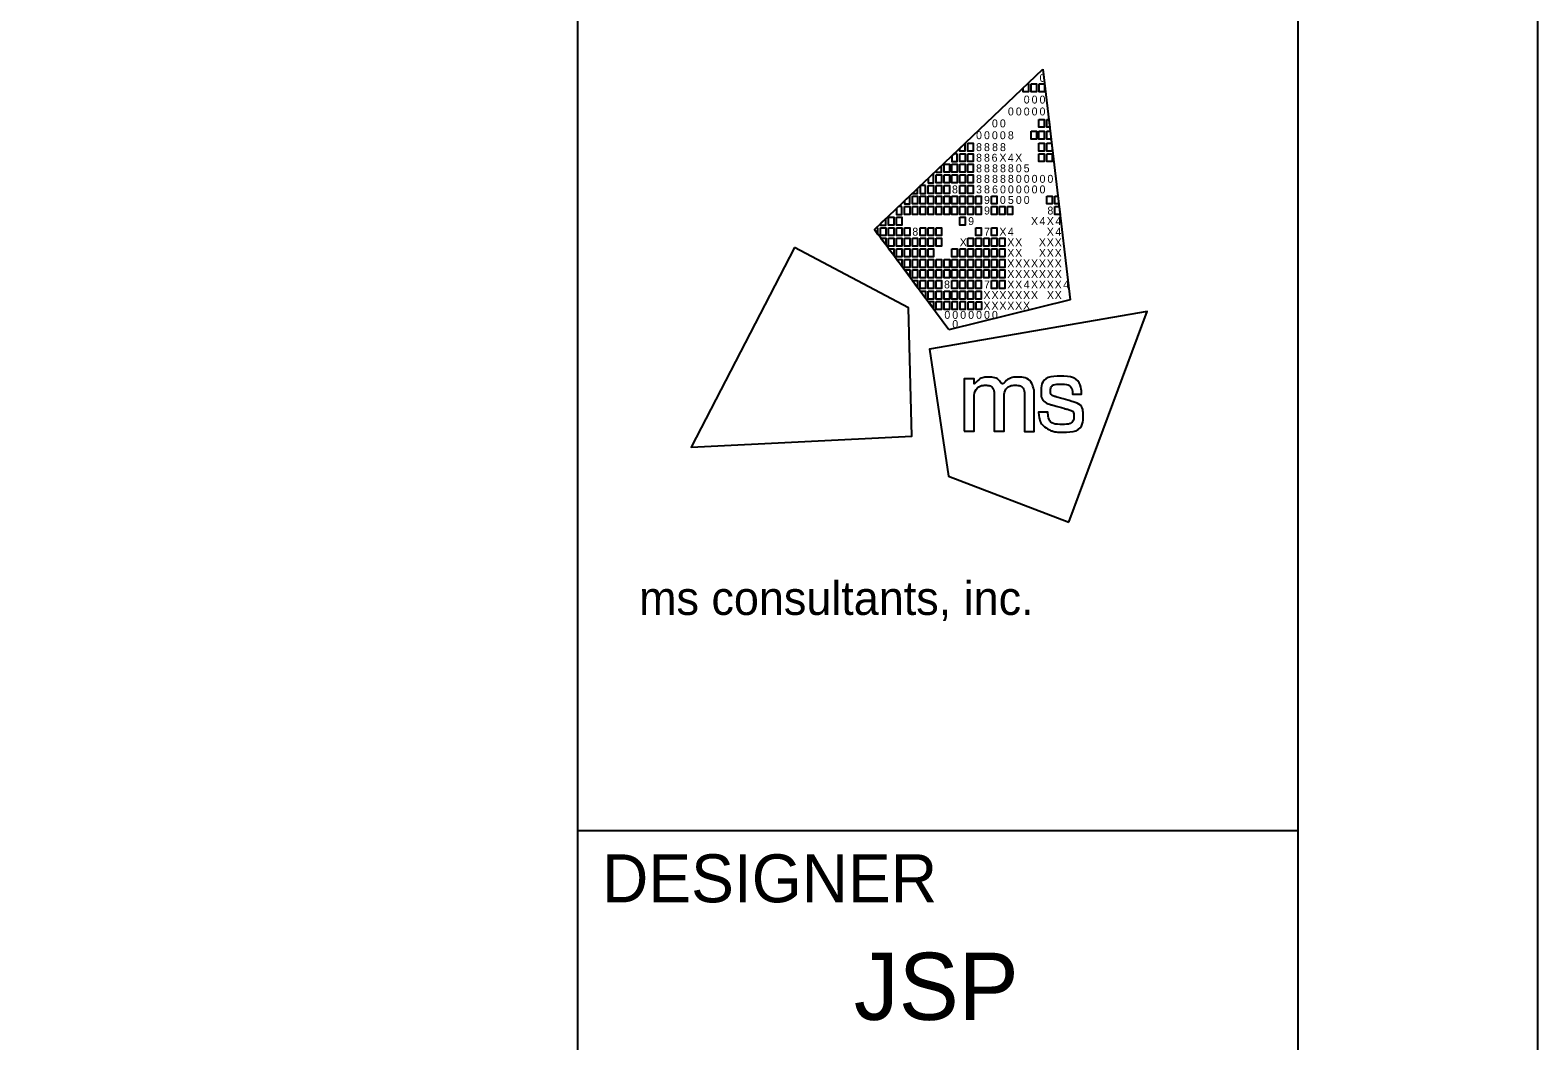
# Model space of a CAD drawing. Extents: x 0 to 680, y 0 to 440.
# Drawn here: x 617.2 to 680, y 41.2 to 83.3 of the extents above; entities that cross this region are included whole.
import ezdxf

# ---------------------------------------------------------------- set-up
doc = ezdxf.new("R2010")
doc.units = 0
for name, color, linetype in [('Default', 7, 'Continuous'), ('SH_Border', 7, 'Continuous'), ('SH_Cut_Line', 7, 'Continuous'), ('SH_Data', 7, 'Continuous')]:
    doc.layers.add(name, color=color, linetype=linetype)

msp = doc.modelspace()

# ---------------------------------------------------------------- linework, layer by layer
at = {"layer": 'Default'}
for p, q in [((652.351, 75.039), (659.376, 81.722)), ((659.376, 81.722), (659.376, 81.722)), ((659.376, 81.722), (660.506, 72.103)), ((655.461, 70.86), (652.351, 75.039)), ((660.506, 72.103), (655.461, 70.86))]:
    msp.add_line(p, q, dxfattribs=at)
for points in [[(658.559, 80.945), (658.738, 81.116), (658.779, 81.116), (658.779, 80.785), (658.559, 80.785)], [(658.888, 81.116), (659.109, 81.116), (659.109, 80.785), (658.888, 80.785)], [(659.219, 81.116), (659.439, 81.116), (659.439, 80.785), (659.219, 80.785)], [(659.212, 79.629), (659.433, 79.629), (659.433, 79.299), (659.212, 79.299)], [(659.542, 79.629), (659.622, 79.629), (659.661, 79.299), (659.542, 79.299)], [(655.908, 78.422), (656.128, 78.632), (656.128, 78.308), (655.908, 78.308)], [(656.246, 78.639), (656.466, 78.639), (656.466, 78.308), (656.246, 78.308)], [(658.883, 79.134), (659.103, 79.134), (659.103, 78.804), (658.883, 78.804)], [(659.212, 79.134), (659.433, 79.134), (659.433, 78.804), (659.212, 78.804)], [(659.212, 78.639), (659.433, 78.639), (659.433, 78.308), (659.212, 78.308)], [(659.542, 79.134), (659.68, 79.134), (659.719, 78.804), (659.542, 78.804)], [(659.542, 78.639), (659.738, 78.639), (659.762, 78.437), (659.762, 78.308), (659.542, 78.308)], [(655.916, 78.198), (656.136, 78.198), (656.136, 77.868), (655.916, 77.868)], [(656.246, 78.198), (656.466, 78.198), (656.466, 77.868), (656.246, 77.868)], [(659.212, 78.198), (659.433, 78.198), (659.433, 77.868), (659.212, 77.868)], [(659.542, 78.198), (659.762, 78.198), (659.762, 77.868), (659.542, 77.868)], [(654.925, 77.318), (655.145, 77.318), (655.145, 76.987), (654.925, 76.987)], [(655.255, 77.758), (655.476, 77.758), (655.476, 77.428), (655.255, 77.428)], [(655.255, 77.318), (655.476, 77.318), (655.476, 76.987), (655.255, 76.987)], [(655.586, 77.758), (655.806, 77.758), (655.806, 77.428), (655.586, 77.428)], [(655.586, 77.318), (655.806, 77.318), (655.806, 76.987), (655.586, 76.987)], [(655.916, 77.758), (656.136, 77.758), (656.136, 77.428), (655.916, 77.428)], [(655.916, 77.318), (656.136, 77.318), (656.136, 76.987), (655.916, 76.987)], [(656.246, 77.758), (656.466, 77.758), (656.466, 77.428), (656.246, 77.428)], [(656.246, 77.318), (656.466, 77.318), (656.466, 76.987), (656.246, 76.987)], [(654.595, 76.877), (654.815, 76.877), (654.815, 76.547), (654.595, 76.547)], [(654.925, 76.877), (655.145, 76.877), (655.145, 76.547), (654.925, 76.547)], [(655.255, 76.877), (655.476, 76.877), (655.476, 76.547), (655.255, 76.547)], [(655.916, 76.877), (656.136, 76.877), (656.136, 76.547), (655.916, 76.547)], [(656.246, 76.877), (656.466, 76.877), (656.466, 76.547), (656.246, 76.547)], [(653.934, 76.437), (654.154, 76.437), (654.154, 76.107), (653.934, 76.107)], [(654.265, 76.437), (654.485, 76.437), (654.485, 76.107), (654.265, 76.107)], [(654.595, 76.437), (654.815, 76.437), (654.815, 76.107), (654.595, 76.107)], [(654.925, 76.437), (655.145, 76.437), (655.145, 76.107), (654.925, 76.107)], [(655.255, 76.437), (655.476, 76.437), (655.476, 76.107), (655.255, 76.107)], [(655.586, 76.437), (655.806, 76.437), (655.806, 76.107), (655.586, 76.107)], [(655.916, 76.437), (656.136, 76.437), (656.136, 76.107), (655.916, 76.107)], [(656.246, 76.437), (656.466, 76.437), (656.466, 76.107), (656.246, 76.107)], [(656.576, 76.437), (656.797, 76.437), (656.797, 76.107), (656.576, 76.107)], [(657.237, 76.437), (657.457, 76.437), (657.457, 76.107), (657.237, 76.107)], [(659.542, 76.437), (659.762, 76.437), (659.762, 76.107), (659.542, 76.107)], [(659.871, 76.437), (659.997, 76.437), (660.036, 76.107), (659.871, 76.107)], [(652.943, 75.556), (653.164, 75.556), (653.164, 75.226), (652.943, 75.226)], [(653.274, 75.556), (653.494, 75.556), (653.494, 75.226), (653.274, 75.226)], [(653.604, 75.996), (653.824, 75.996), (653.824, 75.666), (653.604, 75.666)], [(653.934, 75.996), (654.154, 75.996), (654.154, 75.666), (653.934, 75.666)], [(654.265, 75.996), (654.485, 75.996), (654.485, 75.666), (654.265, 75.666)], [(654.595, 75.996), (654.815, 75.996), (654.815, 75.666), (654.595, 75.666)], [(654.925, 75.996), (655.145, 75.996), (655.145, 75.666), (654.925, 75.666)], [(655.255, 75.996), (655.476, 75.996), (655.476, 75.666), (655.255, 75.666)], [(655.586, 75.996), (655.806, 75.996), (655.806, 75.666), (655.586, 75.666)], [(655.916, 75.996), (656.136, 75.996), (656.136, 75.666), (655.916, 75.666)], [(655.916, 75.556), (656.136, 75.556), (656.136, 75.226), (655.916, 75.226)], [(656.246, 75.996), (656.466, 75.996), (656.466, 75.666), (656.246, 75.666)], [(656.576, 75.996), (656.797, 75.996), (656.797, 75.666), (656.576, 75.666)], [(657.237, 75.996), (657.457, 75.996), (657.457, 75.666), (657.237, 75.666)], [(657.567, 75.996), (657.787, 75.996), (657.787, 75.666), (657.567, 75.666)], [(657.895, 75.996), (658.115, 75.996), (658.115, 75.666), (657.895, 75.666)], [(659.871, 75.996), (660.049, 75.996), (660.088, 75.666), (659.871, 75.666)], [(652.613, 75.116), (652.833, 75.116), (652.833, 74.785), (652.613, 74.785)], [(652.943, 75.116), (653.164, 75.116), (653.164, 74.785), (652.943, 74.785)], [(653.274, 75.116), (653.494, 75.116), (653.494, 74.785), (653.274, 74.785)], [(653.604, 75.116), (653.824, 75.116), (653.824, 74.785), (653.604, 74.785)], [(654.265, 75.116), (654.485, 75.116), (654.485, 74.785), (654.265, 74.785)], [(654.595, 75.116), (654.815, 75.116), (654.815, 74.785), (654.595, 74.785)], [(654.925, 75.116), (655.145, 75.116), (655.145, 74.785), (654.925, 74.785)], [(656.576, 75.116), (656.797, 75.116), (656.797, 74.785), (656.576, 74.785)], [(657.237, 75.116), (657.457, 75.116), (657.457, 74.785), (657.237, 74.785)], [(652.613, 74.675), (652.833, 74.675), (652.833, 74.4)], [(652.943, 74.675), (653.164, 74.675), (653.164, 74.345), (652.943, 74.345)], [(652.943, 74.235), (653.164, 74.235), (653.164, 73.96)], [(653.274, 74.675), (653.494, 74.675), (653.494, 74.345), (653.274, 74.345)], [(653.274, 74.235), (653.494, 74.235), (653.494, 73.905), (653.274, 73.905)], [(653.604, 74.675), (653.824, 74.675), (653.824, 74.345), (653.604, 74.345)], [(653.604, 74.235), (653.824, 74.235), (653.824, 73.905), (653.604, 73.905)], [(653.934, 74.675), (654.154, 74.675), (654.154, 74.345), (653.934, 74.345)], [(653.934, 74.235), (654.154, 74.235), (654.154, 73.905), (653.934, 73.905)], [(654.265, 74.675), (654.485, 74.675), (654.485, 74.345), (654.265, 74.345)], [(654.265, 74.235), (654.485, 74.235), (654.485, 73.905), (654.265, 73.905)], [(654.595, 74.675), (654.815, 74.675), (654.815, 74.345), (654.595, 74.345)], [(654.595, 74.235), (654.815, 74.235), (654.815, 73.905), (654.595, 73.905)], [(654.925, 74.675), (655.145, 74.675), (655.145, 74.345), (654.925, 74.345)], [(655.586, 74.235), (655.806, 74.235), (655.806, 73.905), (655.586, 73.905)], [(655.916, 74.235), (656.136, 74.235), (656.136, 73.905), (655.916, 73.905)], [(656.246, 74.675), (656.466, 74.675), (656.466, 74.345), (656.246, 74.345)], [(656.246, 74.235), (656.466, 74.235), (656.466, 73.905), (656.246, 73.905)], [(656.576, 74.675), (656.797, 74.675), (656.797, 74.345), (656.576, 74.345)], [(656.576, 74.235), (656.797, 74.235), (656.797, 73.905), (656.576, 73.905)], [(656.907, 74.675), (657.127, 74.675), (657.127, 74.345), (656.907, 74.345)], [(656.907, 74.235), (657.127, 74.235), (657.127, 73.905), (656.907, 73.905)], [(657.237, 74.675), (657.457, 74.675), (657.457, 74.345), (657.237, 74.345)], [(657.237, 74.235), (657.457, 74.235), (657.457, 73.905), (657.237, 73.905)], [(657.567, 74.675), (657.787, 74.675), (657.787, 74.345), (657.567, 74.345)], [(657.567, 74.235), (657.787, 74.235), (657.787, 73.905), (657.567, 73.905)], [(653.274, 73.795), (653.494, 73.795), (653.494, 73.519)], [(653.494, 73.795), (653.494, 73.795), (653.494, 73.795)], [(653.604, 73.795), (653.824, 73.795), (653.824, 73.464), (653.604, 73.464)], [(653.934, 73.795), (654.154, 73.795), (654.154, 73.464), (653.934, 73.464)], [(654.265, 73.795), (654.485, 73.795), (654.485, 73.464), (654.265, 73.464)], [(654.595, 73.795), (654.815, 73.795), (654.815, 73.464), (654.595, 73.464)], [(654.925, 73.795), (655.145, 73.795), (655.145, 73.464), (654.925, 73.464)], [(655.255, 73.795), (655.476, 73.795), (655.476, 73.464), (655.255, 73.464)], [(655.586, 73.795), (655.806, 73.795), (655.806, 73.464), (655.586, 73.464)], [(655.916, 73.795), (656.136, 73.795), (656.136, 73.464), (655.916, 73.464)], [(656.246, 73.795), (656.466, 73.795), (656.466, 73.464), (656.246, 73.464)], [(656.576, 73.795), (656.797, 73.795), (656.797, 73.464), (656.576, 73.464)], [(656.907, 73.795), (657.127, 73.795), (657.127, 73.464), (656.907, 73.464)], [(657.237, 73.795), (657.457, 73.795), (657.457, 73.464), (657.237, 73.464)], [(657.567, 73.795), (657.787, 73.795), (657.787, 73.464), (657.567, 73.464)], [(653.604, 73.354), (653.824, 73.354), (653.824, 73.079)], [(654.155, 72.611), (653.931, 72.915), (654.155, 72.915)], [(653.934, 73.354), (654.154, 73.354), (654.154, 73.024), (653.934, 73.024)], [(654.265, 73.354), (654.485, 73.354), (654.485, 73.024), (654.265, 73.024)], [(654.265, 72.914), (654.485, 72.914), (654.485, 72.584), (654.265, 72.584)], [(654.595, 73.354), (654.815, 73.354), (654.815, 73.024), (654.595, 73.024)], [(654.595, 72.914), (654.815, 72.914), (654.815, 72.584), (654.595, 72.584)], [(654.925, 73.354), (655.145, 73.354), (655.145, 73.024), (654.925, 73.024)], [(654.925, 72.914), (655.145, 72.914), (655.145, 72.584), (654.925, 72.584)], [(655.255, 73.354), (655.476, 73.354), (655.476, 73.024), (655.255, 73.024)], [(655.586, 73.354), (655.806, 73.354), (655.806, 73.024), (655.586, 73.024)], [(655.586, 72.914), (655.806, 72.914), (655.806, 72.584), (655.586, 72.584)], [(655.916, 73.354), (656.136, 73.354), (656.136, 73.024), (655.916, 73.024)], [(655.916, 72.914), (656.136, 72.914), (656.136, 72.584), (655.916, 72.584)], [(656.246, 73.354), (656.466, 73.354), (656.466, 73.024), (656.246, 73.024)], [(656.246, 72.914), (656.466, 72.914), (656.466, 72.584), (656.246, 72.584)], [(656.576, 73.354), (656.797, 73.354), (656.797, 73.024), (656.576, 73.024)], [(656.576, 72.914), (656.797, 72.914), (656.797, 72.584), (656.576, 72.584)], [(656.907, 73.354), (657.127, 73.354), (657.127, 73.024), (656.907, 73.024)], [(657.237, 73.354), (657.457, 73.354), (657.457, 73.024), (657.237, 73.024)], [(657.237, 72.914), (657.457, 72.914), (657.457, 72.584), (657.237, 72.584)], [(657.567, 73.354), (657.787, 73.354), (657.787, 73.024), (657.567, 73.024)], [(657.567, 72.914), (657.787, 72.914), (657.787, 72.584), (657.567, 72.584)], [(654.48, 72.164), (654.264, 72.474), (654.484, 72.474)], [(654.595, 72.473), (654.815, 72.473), (654.815, 72.143), (654.595, 72.143)], [(654.925, 72.473), (655.145, 72.473), (655.145, 72.143), (654.925, 72.143)], [(655.255, 72.473), (655.476, 72.473), (655.476, 72.143), (655.255, 72.143)], [(655.586, 72.473), (655.806, 72.473), (655.806, 72.143), (655.586, 72.143)], [(655.916, 72.473), (656.136, 72.473), (656.136, 72.143), (655.916, 72.143)], [(656.246, 72.473), (656.466, 72.473), (656.466, 72.143), (656.246, 72.143)], [(656.576, 72.473), (656.797, 72.473), (656.797, 72.143), (656.576, 72.143)], [(654.605, 72.034), (654.815, 72.034), (654.816, 71.75)], [(654.927, 72.034), (655.147, 72.034), (655.147, 71.704), (654.927, 71.704)], [(655.26, 72.034), (655.48, 72.034), (655.48, 71.704), (655.26, 71.704)], [(655.588, 72.034), (655.808, 72.034), (655.808, 71.704), (655.588, 71.704)], [(655.921, 72.034), (656.141, 72.034), (656.141, 71.704), (655.921, 71.704)], [(656.259, 72.033), (656.48, 72.033), (656.48, 71.703), (656.259, 71.703)], [(656.593, 72.033), (656.813, 72.033), (656.813, 71.703), (656.593, 71.703)]]:
    msp.add_lwpolyline(points, close=True, dxfattribs=at)
for points in [[(655.806, 78.198), (655.672, 78.198), (655.586, 78.116), (655.586, 77.868), (655.806, 77.868), (655.806, 78.198)], [(654.815, 77.383), (654.595, 77.173), (654.595, 76.987), (654.815, 76.987), (654.815, 77.383)], [(655.145, 77.697), (654.925, 77.488), (654.925, 77.428), (655.145, 77.428), (655.145, 77.697)], [(654.154, 76.754), (653.936, 76.547), (654.154, 76.547), (654.154, 76.754)], [(654.485, 76.877), (654.284, 76.877), (654.265, 76.859), (654.265, 76.547), (654.485, 76.547), (654.485, 76.877)], [(653.824, 76.44), (653.604, 76.231), (653.604, 76.107), (653.824, 76.107), (653.824, 76.44)], [(652.833, 75.497), (652.613, 75.288), (652.613, 75.226), (652.833, 75.226), (652.833, 75.497)], [(653.494, 75.996), (653.358, 75.996), (653.274, 75.916), (653.274, 75.666), (653.494, 75.666), (653.494, 75.996)], [(652.503, 75.116), (652.432, 75.116), (652.351, 75.039), (652.503, 74.835), (652.503, 75.116)], [(649.025, 74.297), (644.719, 65.976), (653.913, 66.429), (653.768, 71.783), (649.025, 74.297)], [(660.459, 62.844), (663.718, 71.628), (654.648, 70.058), (655.444, 64.762), (660.459, 62.844)]]:
    msp.add_lwpolyline(points, dxfattribs=at)
for points in [[(656.096, 66.63), (656.096, 66.63), (656.096, 68.818), (656.096, 68.818), (656.096, 68.818), (656.51, 68.818), (656.51, 68.818), (656.51, 68.818), (656.51, 68.595), (656.51, 68.595), (656.692, 68.799), (656.914, 68.889), (657.111, 68.889), (657.377, 68.889), (657.583, 68.744), (657.674, 68.533), (657.83, 68.761), (658.101, 68.892), (658.332, 68.892), (658.651, 68.892), (658.902, 68.7), (658.988, 68.425), (658.989, 68.425), (658.989, 68.424), (658.989, 68.423), (659.003, 68.379), (659.013, 68.345), (659.013, 68.141), (659.013, 68.141), (659.013, 66.629), (659.013, 66.629), (659.013, 66.629), (658.606, 66.629), (658.606, 66.629), (658.606, 66.629), (658.606, 68.096), (658.606, 68.096), (658.606, 68.402), (658.438, 68.548), (658.221, 68.548), (657.991, 68.548), (657.759, 68.341), (657.759, 68.003), (657.759, 68.003), (657.759, 66.63), (657.759, 66.63), (657.759, 66.63), (657.349, 66.63), (657.349, 66.63), (657.349, 66.63), (657.349, 68.118), (657.349, 68.118), (657.349, 68.406), (657.177, 68.548), (656.993, 68.548), (656.768, 68.548), (656.508, 68.341), (656.508, 67.924), (656.508, 67.924), (656.508, 66.63), (656.508, 66.63), (656.508, 66.63), (656.096, 66.63), (656.096, 66.63)], [(659.192, 67.417), (659.192, 67.417), (659.19, 67.434), (659.19, 67.434), (659.19, 67.434), (659.207, 67.434), (659.207, 67.434), (659.207, 67.434), (659.566, 67.434), (659.566, 67.434), (659.566, 67.434), (659.579, 67.434), (659.579, 67.434), (659.579, 67.434), (659.58, 67.42), (659.58, 67.42), (659.606, 67.108), (659.774, 66.92), (660.18, 66.92), (660.546, 66.92), (660.667, 67.109), (660.667, 67.262), (660.667, 67.463), (660.512, 67.515), (660.351, 67.561), (660.351, 67.561), (659.74, 67.734), (659.74, 67.734), (659.441, 67.818), (659.296, 68.037), (659.296, 68.285), (659.296, 68.606), (659.536, 68.923), (660.105, 68.923), (660.697, 68.923), (660.979, 68.57), (660.979, 68.189), (660.979, 68.189), (660.979, 68.174), (660.979, 68.174), (660.979, 68.174), (660.964, 68.174), (660.964, 68.174), (660.964, 68.174), (660.625, 68.174), (660.625, 68.174), (660.625, 68.174), (660.611, 68.174), (660.611, 68.174), (660.611, 68.174), (660.61, 68.189), (660.61, 68.189), (660.604, 68.416), (660.454, 68.599), (660.112, 68.599), (659.782, 68.599), (659.686, 68.435), (659.686, 68.314), (659.686, 68.216), (659.738, 68.118), (659.918, 68.067), (659.918, 68.067), (660.51, 67.897), (660.51, 67.897), (660.925, 67.777), (661.054, 67.555), (661.054, 67.279), (661.054, 66.925), (660.82, 66.597), (660.175, 66.597), (659.904, 66.597), (659.754, 66.642), (659.646, 66.696), (659.381, 66.829), (659.219, 67.072), (659.192, 67.417)]]:
    msp.add_open_spline(points, degree=3, dxfattribs=at)
at = {"layer": 'SH_Border'}
for p, q in [((640, 10), (640, 430)), ((640, 50), (670, 50))]:
    msp.add_line(p, q, dxfattribs=at)
msp.add_lwpolyline([(30, 430), (670, 430), (670, 10), (30, 10)], close=True, dxfattribs=at)
at = {"layer": 'SH_Cut_Line'}
msp.add_lwpolyline([(0, 0), (680, 0), (680, 440), (0, 440)], close=True, dxfattribs=at)
at = {"layer": 'SH_Data'}
msp.add_line((655, 70), (655, 70), dxfattribs=at)

# ---------------------------------------------------------------- texts
at = {"layer": 'Default'}
for s, p in [('0', (659.235, 81.194)), ('0', (658.576, 80.29)), ('0', (658.905, 80.29)), ('0', (659.235, 80.29)), ('0', (657.917, 79.795)), ('0', (658.246, 79.795)), ('0', (658.576, 79.795)), ('0', (658.905, 79.795)), ('0', (659.235, 79.795)), ('0', (657.251, 79.299)), ('0', (657.581, 79.299)), ('0', (656.59, 78.804)), ('8', (656.59, 78.308)), ('0', (656.921, 78.804)), ('8', (656.92, 78.308)), ('0', (657.251, 78.804)), ('8', (657.257, 78.308)), ('0', (657.581, 78.804)), ('8', (657.587, 78.308)), ('8', (657.916, 78.804)), ('8', (656.59, 77.868)), ('8', (656.92, 77.868)), ('6', (657.237, 77.868)), ('X', (657.562, 77.868)), ('4', (657.917, 77.868)), ('X', (658.22, 77.868)), ('8', (656.59, 77.426)), ('8', (656.59, 76.987)), ('8', (656.92, 77.426)), ('8', (656.92, 76.987)), ('8', (657.257, 77.426)), ('8', (657.257, 76.987)), ('8', (657.588, 77.426)), ('8', (657.588, 76.987)), ('8', (657.916, 77.426)), ('8', (657.916, 76.987)), ('0', (658.246, 77.426)), ('0', (658.246, 76.987)), ('5', (658.574, 77.426)), ('0', (658.576, 76.987)), ('0', (658.905, 76.987)), ('0', (659.235, 76.987)), ('0', (659.564, 76.987)), ('8', (655.586, 76.547)), ('3', (656.59, 76.547)), ('8', (656.92, 76.547)), ('6', (657.258, 76.547)), ('0', (657.588, 76.547)), ('0', (657.917, 76.547)), ('0', (658.246, 76.547)), ('0', (658.576, 76.547)), ('0', (658.905, 76.547)), ('0', (659.235, 76.547)), ('9', (656.921, 76.107)), ('0', (657.581, 76.107)), ('5', (657.916, 76.107)), ('0', (658.246, 76.107)), ('0', (658.576, 76.107)), ('9', (656.26, 75.226)), ('9', (656.921, 75.666)), ('X', (658.879, 75.226)), ('4', (659.234, 75.226)), ('X', (659.538, 75.226)), ('8', (659.563, 75.666)), ('4', (659.893, 75.226)), ('8', (653.934, 74.785)), ('7', (656.921, 74.785)), ('X', (657.562, 74.785)), ('4', (657.917, 74.785)), ('X', (659.538, 74.785)), ('4', (659.893, 74.785)), ('X', (655.911, 74.345)), ('X', (657.891, 74.345)), ('X', (657.891, 73.905)), ('X', (658.22, 74.345)), ('X', (658.22, 73.905)), ('X', (659.208, 74.345)), ('X', (659.208, 73.905)), ('X', (659.538, 74.345)), ('X', (659.538, 73.905)), ('X', (659.867, 74.345)), ('X', (659.867, 73.905)), ('X', (657.891, 73.464)), ('X', (658.22, 73.464)), ('X', (658.549, 73.464)), ('X', (658.879, 73.464)), ('X', (659.208, 73.464)), ('X', (659.538, 73.464)), ('X', (659.867, 73.464)), ('8', (655.255, 72.584)), ('7', (656.921, 72.584)), ('X', (657.891, 73.024)), ('X', (657.891, 72.584)), ('X', (658.22, 73.024)), ('X', (658.22, 72.584)), ('X', (658.549, 73.024)), ('4', (658.576, 72.584)), ('X', (658.879, 73.024)), ('X', (658.879, 72.584)), ('X', (659.208, 73.024)), ('X', (659.208, 72.584)), ('X', (659.538, 73.024)), ('X', (659.538, 72.584)), ('X', (659.867, 73.024)), ('X', (659.867, 72.584)), ('4', (660.223, 72.584)), ('X', (656.894, 72.143)), ('X', (657.232, 72.143)), ('X', (657.561, 72.143)), ('X', (657.891, 72.143)), ('X', (658.22, 72.143)), ('X', (658.549, 72.143)), ('X', (658.879, 72.143)), ('X', (659.544, 72.143)), ('X', (659.867, 72.143)), ('0', (655.269, 71.318)), ('0', (655.599, 71.318)), ('0', (655.93, 71.318)), ('0', (656.26, 71.318)), ('0', (656.59, 71.318)), ('X', (656.894, 71.703)), ('0', (656.921, 71.318)), ('X', (657.232, 71.703)), ('0', (657.251, 71.318)), ('X', (657.561, 71.703)), ('X', (657.891, 71.703)), ('X', (658.22, 71.703)), ('X', (658.549, 71.703)), ('0', (655.599, 70.933))]:
    msp.add_text(s, height=0.33, rotation=360, dxfattribs=at).set_placement(p)
at = {"layer": 'SH_Border'}
msp.add_text('ms consultants, inc.', height=1.4, rotation=360, dxfattribs=at).set_placement((642.547, 58.978))
at = {"layer": 'SH_Data'}
for s, height, p in [('DESIGNER', 2, (641, 47)), ('JSP', 2.8, (651.497, 42.1))]:
    msp.add_text(s, height=height, dxfattribs=at).set_placement(p)

doc.saveas('drawing.dxf')
